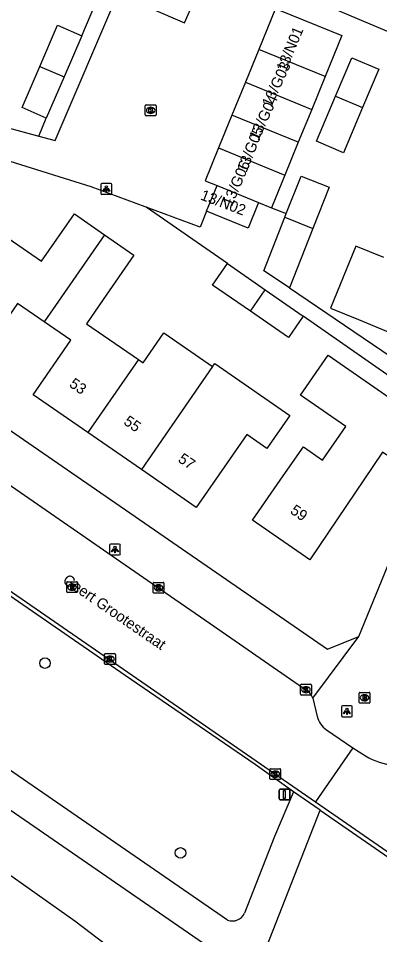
# Model space of a CAD drawing. Extents: x 162812 to 163818, y 381639 to 382470.
# Drawn here: x 163284.9 to 163318.4, y 381864.8 to 381949.7 of the extents above; entities that cross this region are included whole.
import ezdxf

# ---------------------------------------------------------------- set-up
doc = ezdxf.new("R2010")
doc.units = 0
for name, color, linetype in [('IMGEO_Boom', 7, 'Continuous'), ('IMGEO_Brandkraan', 7, 'Continuous'), ('IMGEO_Groenvoorziening', 7, 'Continuous'), ('IMGEO_Kolk', 7, 'Continuous'), ('IMGEO_Lichtpunt', 7, 'Continuous'), ('IMGEO_Openbare_ruimte_label', 7, 'Continuous'), ('IMGEO_Pand', 7, 'Continuous'), ('IMGEO_Pand_nummerreeks', 7, 'Continuous'), ('IMGEO_Rijbaan_lokaal_gesloten', 7, 'Continuous'), ('IMGEO_Rijbaan_lokaal_open', 7, 'Continuous'), ('IMGEO_Rioolput', 7, 'Continuous'), ('IMGEO_Verkeersbordpaal', 7, 'Continuous'), ('IMGEO_Voetpad_gesloten', 7, 'Continuous'), ('IMGEO_Voetpad_open', 7, 'Continuous')]:
    doc.layers.add(name, color=color, linetype=linetype)

msp = doc.modelspace()

# ---------------------------------------------------------------- linework, layer by layer
at = {"layer": 'IMGEO_Boom'}
for centre in [(163287.407, 381890.005), (163299.943, 381872.421)]:
    msp.add_circle(centre, 0.489, dxfattribs=at)
at = {"layer": 'IMGEO_Brandkraan'}
for p, q in [((163316.473, 381886.368), (163316.473, 381887.22)), ((163316.548, 381887.294), (163317.4, 381887.294)), ((163317.474, 381887.22), (163317.474, 381886.368)), ((163317.4, 381886.294), (163316.548, 381886.294)), ((163316.984, 381886.514), (163316.959, 381886.514)), ((163316.961, 381887.074), (163316.986, 381887.074))]:
    msp.add_line(p, q, dxfattribs=at)
for points in [[(163316.473, 381886.368), (163316.473, 381887.22)], [(163316.548, 381887.294), (163317.4, 381887.294)], [(163317.474, 381887.22), (163317.474, 381886.368)], [(163317.4, 381886.294), (163316.548, 381886.294)], [(163316.821, 381886.994), (163316.821, 381886.594), (163317.034, 381886.594)], [(163317.052, 381886.994), (163316.821, 381886.994)], [(163317, 381886.913), (163316.946, 381886.913), (163316.946, 381886.837)], [(163316.946, 381886.837), (163316.999, 381886.837)], [(163317.008, 381886.761), (163316.946, 381886.761), (163316.946, 381886.68)], [(163316.946, 381886.68), (163317.008, 381886.68)]]:
    msp.add_lwpolyline(points, dxfattribs=at)
for centre, radius, start, end in [((163316.55, 381887.218), 0.0765, 91.55205, 178.44795), ((163316.55, 381887.218), 0.0765, 91.55205, 178.44795), ((163317.398, 381887.218), 0.0765, 1.55205, 88.44795), ((163317.398, 381887.218), 0.0765, 1.55205, 88.44795), ((163316.55, 381886.37), 0.0765, 181.55205, 268.44795), ((163316.55, 381886.37), 0.0765, 181.55205, 268.44795), ((163317.001, 381886.875), 0.0379, 267.82845, 90.93552), ((163317.009, 381886.72), 0.0404, 269.87594, 90.50774), ((163317.04, 381886.845), 0.251, 268.66757, 293.53466), ((163317.056, 381886.849), 0.145, 59.4692, 91.53667), ((163317.081, 381886.896), 0.0922, 285.51372, 58.15012), ((163317.086, 381886.704), 0.105, 301.31148, 78.98903), ((163317.398, 381886.37), 0.0765, 271.55205, 358.44795), ((163317.398, 381886.37), 0.0765, 271.55205, 358.44795)]:
    msp.add_arc(centre, radius, start, end, dxfattribs=at)
for centre, major_axis, ratio, start_param, end_param in [((163316.96, 381886.794), (-0.387, 0.002), 0.722429, 4.712389, 7.853982), ((163316.985, 381886.794), (-0.39, 0.002), 0.717154, 1.570796, 4.712389)]:
    msp.add_ellipse(centre, major_axis=major_axis, ratio=ratio, start_param=start_param, end_param=end_param, dxfattribs=at)
at = {"layer": 'IMGEO_Groenvoorziening'}
msp.add_lwpolyline([(163279.685, 381873.538), (163290.178, 381866.115), (163314.756, 381847.403)], dxfattribs=at)
at = {"layer": 'IMGEO_Kolk'}
for p, q in [((163296.691, 381940.792), (163296.691, 381941.644)), ((163296.766, 381941.718), (163297.618, 381941.718)), ((163297.179, 381941.498), (163297.204, 381941.498)), ((163297.692, 381941.644), (163297.692, 381940.792)), ((163297.618, 381940.718), (163296.766, 381940.718)), ((163297.202, 381940.938), (163297.177, 381940.938)), ((163297.413, 381896.555), (163297.413, 381897.407)), ((163297.488, 381897.481), (163298.34, 381897.481)), ((163298.414, 381897.407), (163298.414, 381896.555)), ((163298.34, 381896.481), (163297.488, 381896.481)), ((163297.924, 381896.701), (163297.899, 381896.701)), ((163297.901, 381897.261), (163297.926, 381897.261)), ((163292.916, 381889.956), (163292.916, 381890.808)), ((163292.991, 381890.882), (163293.843, 381890.882)), ((163293.404, 381890.662), (163293.429, 381890.662)), ((163293.917, 381890.808), (163293.917, 381889.956)), ((163293.843, 381889.882), (163292.991, 381889.882)), ((163293.427, 381890.102), (163293.402, 381890.102)), ((163311.054, 381887.116), (163311.054, 381887.968)), ((163311.129, 381888.042), (163311.981, 381888.042)), ((163312.055, 381887.968), (163312.055, 381887.116)), ((163311.565, 381887.262), (163311.54, 381887.262)), ((163311.542, 381887.822), (163311.567, 381887.822)), ((163311.981, 381887.042), (163311.129, 381887.042)), ((163308.21, 381879.291), (163308.21, 381880.143)), ((163308.285, 381880.217), (163309.137, 381880.217)), ((163308.698, 381879.997), (163308.723, 381879.997)), ((163309.211, 381880.143), (163309.211, 381879.291)), ((163309.137, 381879.217), (163308.285, 381879.217)), ((163308.721, 381879.437), (163308.696, 381879.437))]:
    msp.add_line(p, q, dxfattribs=at)
for points in [[(163296.691, 381940.792), (163296.691, 381941.644)], [(163296.766, 381941.718), (163297.618, 381941.718)], [(163297.692, 381941.644), (163297.692, 381940.792)], [(163297.618, 381940.718), (163296.766, 381940.718)], [(163297.012, 381941.418), (163297.135, 381941.418), (163297.135, 381941.267), (163297.265, 381941.418), (163297.429, 381941.418), (163297.283, 381941.267), (163297.436, 381941.018), (163297.284, 381941.018), (163297.199, 381941.182), (163297.135, 381941.115), (163297.135, 381941.018), (163297.012, 381941.018), (163297.012, 381941.418)], [(163297.413, 381896.555), (163297.413, 381897.407)], [(163297.488, 381897.481), (163298.34, 381897.481)], [(163298.414, 381897.407), (163298.414, 381896.555)], [(163298.34, 381896.481), (163297.488, 381896.481)], [(163297.734, 381897.181), (163297.857, 381897.181), (163297.857, 381897.03), (163297.987, 381897.181), (163298.151, 381897.181), (163298.005, 381897.03), (163298.158, 381896.781), (163298.006, 381896.781), (163297.921, 381896.945), (163297.857, 381896.878), (163297.857, 381896.781), (163297.734, 381896.781), (163297.734, 381897.181)], [(163292.916, 381889.956), (163292.916, 381890.808)], [(163292.991, 381890.882), (163293.843, 381890.882)], [(163293.237, 381890.582), (163293.36, 381890.582), (163293.36, 381890.431), (163293.49, 381890.582), (163293.654, 381890.582), (163293.508, 381890.431), (163293.661, 381890.182), (163293.509, 381890.182), (163293.424, 381890.346), (163293.36, 381890.279), (163293.36, 381890.182), (163293.237, 381890.182), (163293.237, 381890.582)], [(163293.917, 381890.808), (163293.917, 381889.956)], [(163293.843, 381889.882), (163292.991, 381889.882)], [(163311.054, 381887.116), (163311.054, 381887.968)], [(163311.129, 381888.042), (163311.981, 381888.042)], [(163312.055, 381887.968), (163312.055, 381887.116)], [(163311.375, 381887.742), (163311.498, 381887.742), (163311.498, 381887.591), (163311.628, 381887.742), (163311.792, 381887.742), (163311.646, 381887.591), (163311.799, 381887.342), (163311.647, 381887.342), (163311.562, 381887.506), (163311.498, 381887.439), (163311.498, 381887.342), (163311.375, 381887.342), (163311.375, 381887.742)], [(163311.981, 381887.042), (163311.129, 381887.042)], [(163308.21, 381879.291), (163308.21, 381880.143)], [(163308.285, 381880.217), (163309.137, 381880.217)], [(163308.531, 381879.917), (163308.654, 381879.917), (163308.654, 381879.766), (163308.784, 381879.917), (163308.948, 381879.917), (163308.802, 381879.766), (163308.955, 381879.517), (163308.803, 381879.517), (163308.718, 381879.681), (163308.654, 381879.614), (163308.654, 381879.517), (163308.531, 381879.517), (163308.531, 381879.917)], [(163309.211, 381880.143), (163309.211, 381879.291)], [(163309.137, 381879.217), (163308.285, 381879.217)]]:
    msp.add_lwpolyline(points, dxfattribs=at)
for centre, start, end in [((163296.768, 381941.642), 91.55205, 178.44795), ((163296.768, 381941.642), 91.55205, 178.44795), ((163297.616, 381941.642), 1.55205, 88.44795), ((163297.616, 381941.642), 1.55205, 88.44795), ((163296.768, 381940.794), 181.55205, 268.44795), ((163296.768, 381940.794), 181.55205, 268.44795), ((163297.616, 381940.794), 271.55205, 358.44795), ((163297.616, 381940.794), 271.55205, 358.44795), ((163297.49, 381897.405), 91.55205, 178.44795), ((163297.49, 381897.405), 91.55205, 178.44795), ((163298.338, 381897.405), 1.55205, 88.44795), ((163298.338, 381897.405), 1.55205, 88.44795), ((163297.49, 381896.557), 181.55205, 268.44795), ((163297.49, 381896.557), 181.55205, 268.44795), ((163298.338, 381896.557), 271.55205, 358.44795), ((163298.338, 381896.557), 271.55205, 358.44795), ((163292.993, 381890.806), 91.55205, 178.44795), ((163292.993, 381890.806), 91.55205, 178.44795), ((163293.841, 381890.806), 1.55205, 88.44795), ((163293.841, 381890.806), 1.55205, 88.44795), ((163292.993, 381889.958), 181.55205, 268.44795), ((163292.993, 381889.958), 181.55205, 268.44795), ((163293.841, 381889.958), 271.55205, 358.44795), ((163293.841, 381889.958), 271.55205, 358.44795), ((163311.131, 381887.966), 91.55205, 178.44795), ((163311.131, 381887.966), 91.55205, 178.44795), ((163311.979, 381887.966), 1.55205, 88.44795), ((163311.979, 381887.966), 1.55205, 88.44795), ((163311.131, 381887.118), 181.55205, 268.44795), ((163311.131, 381887.118), 181.55205, 268.44795), ((163311.979, 381887.118), 271.55205, 358.44795), ((163311.979, 381887.118), 271.55205, 358.44795), ((163308.287, 381880.141), 91.55205, 178.44795), ((163308.287, 381880.141), 91.55205, 178.44795), ((163309.135, 381880.141), 1.55205, 88.44795), ((163309.135, 381880.141), 1.55205, 88.44795), ((163308.287, 381879.293), 181.55205, 268.44795), ((163308.287, 381879.293), 181.55205, 268.44795), ((163309.135, 381879.293), 271.55205, 358.44795), ((163309.135, 381879.293), 271.55205, 358.44795)]:
    msp.add_arc(centre, 0.0765, start, end, dxfattribs=at)
for centre, major_axis, ratio, start_param, end_param in [((163297.178, 381941.218), (-0.387, 0.002), 0.722429, 4.712389, 7.853982), ((163297.203, 381941.218), (-0.39, 0.002), 0.717154, 1.570796, 4.712389), ((163297.9, 381896.981), (-0.387, 0.002), 0.722429, 4.712389, 7.853982), ((163297.925, 381896.981), (-0.39, 0.002), 0.717154, 1.570796, 4.712389), ((163293.403, 381890.382), (-0.387, 0.002), 0.722429, 4.712389, 7.853982), ((163293.428, 381890.382), (-0.39, 0.002), 0.717154, 1.570796, 4.712389), ((163311.541, 381887.542), (-0.387, 0.002), 0.722429, 4.712389, 7.853982), ((163311.566, 381887.542), (-0.39, 0.002), 0.717154, 1.570796, 4.712389), ((163308.697, 381879.717), (-0.387, 0.002), 0.722429, 4.712389, 7.853982), ((163308.722, 381879.717), (-0.39, 0.002), 0.717154, 1.570796, 4.712389)]:
    msp.add_ellipse(centre, major_axis=major_axis, ratio=ratio, start_param=start_param, end_param=end_param, dxfattribs=at)
at = {"layer": 'IMGEO_Lichtpunt'}
for p, q in [((163292.585, 381934.337), (163292.585, 381933.53)), ((163292.585, 381934.337), (163292.585, 381933.53)), ((163293.487, 381934.432), (163292.679, 381934.432)), ((163293.487, 381934.432), (163292.679, 381934.432)), ((163293.581, 381933.53), (163293.581, 381934.337)), ((163293.581, 381933.53), (163293.581, 381934.337)), ((163292.679, 381933.436), (163293.487, 381933.436)), ((163292.679, 381933.436), (163293.487, 381933.436)), ((163293.383, 381900.937), (163293.383, 381900.13)), ((163293.383, 381900.937), (163293.383, 381900.13)), ((163294.285, 381901.032), (163293.477, 381901.032)), ((163294.285, 381901.032), (163293.477, 381901.032)), ((163294.379, 381900.13), (163294.379, 381900.937)), ((163294.379, 381900.13), (163294.379, 381900.937)), ((163293.477, 381900.036), (163294.285, 381900.036)), ((163293.477, 381900.036), (163294.285, 381900.036)), ((163314.846, 381885.943), (163314.846, 381885.136)), ((163314.846, 381885.943), (163314.846, 381885.136)), ((163315.748, 381886.038), (163314.94, 381886.038)), ((163315.748, 381886.038), (163314.94, 381886.038)), ((163315.842, 381885.136), (163315.842, 381885.943)), ((163315.842, 381885.136), (163315.842, 381885.943)), ((163314.94, 381885.042), (163315.748, 381885.042)), ((163314.94, 381885.042), (163315.748, 381885.042))]:
    msp.add_line(p, q, dxfattribs=at)
for points in [[(163292.959, 381934.001), (163292.998, 381933.973), (163292.81, 381933.711), (163292.772, 381933.738), (163292.959, 381934.001)], [(163293.061, 381933.953), (163293.108, 381933.953), (163293.108, 381933.631), (163293.061, 381933.631), (163293.061, 381933.953)], [(163293.171, 381933.973), (163293.209, 381934), (163293.396, 381933.738), (163293.357, 381933.71), (163293.171, 381933.973)], [(163293.757, 381900.601), (163293.796, 381900.573), (163293.608, 381900.311), (163293.57, 381900.338), (163293.757, 381900.601)], [(163293.859, 381900.553), (163293.906, 381900.553), (163293.906, 381900.231), (163293.859, 381900.231), (163293.859, 381900.553)], [(163293.969, 381900.573), (163294.007, 381900.6), (163294.194, 381900.338), (163294.155, 381900.31), (163293.969, 381900.573)], [(163315.22, 381885.607), (163315.259, 381885.579), (163315.071, 381885.317), (163315.033, 381885.344), (163315.22, 381885.607)], [(163315.322, 381885.559), (163315.369, 381885.559), (163315.369, 381885.237), (163315.322, 381885.237), (163315.322, 381885.559)], [(163315.432, 381885.579), (163315.47, 381885.606), (163315.657, 381885.344), (163315.618, 381885.316), (163315.432, 381885.579)]]:
    msp.add_lwpolyline(points, dxfattribs=at)
for centre in [(163293.084, 381934.135), (163293.882, 381900.735), (163315.345, 381885.741)]:
    msp.add_circle(centre, 0.0994, dxfattribs=at)
for centre, start, end in [((163292.679, 381934.337), 90, 180), ((163292.679, 381934.337), 90, 180), ((163293.487, 381934.337), 0, 90), ((163293.487, 381934.337), 0, 90), ((163292.679, 381933.53), 180, 270), ((163292.679, 381933.53), 180, 270), ((163293.487, 381933.53), 270, 0), ((163293.487, 381933.53), 270, 360), ((163293.477, 381900.937), 90, 180), ((163293.477, 381900.937), 90, 180), ((163294.285, 381900.937), 0, 90), ((163294.285, 381900.937), 0, 90), ((163293.477, 381900.13), 180, 270), ((163293.477, 381900.13), 180, 270), ((163294.285, 381900.13), 270, 0), ((163294.285, 381900.13), 270, 360), ((163314.94, 381885.943), 90, 180), ((163314.94, 381885.943), 90, 180), ((163315.748, 381885.943), 0, 90), ((163315.748, 381885.943), 0, 90), ((163314.94, 381885.136), 180, 270), ((163314.94, 381885.136), 180, 270), ((163315.748, 381885.136), 270, 0), ((163315.748, 381885.136), 270, 360)]:
    msp.add_arc(centre, 0.0946, start, end, dxfattribs=at)
at = {"layer": 'IMGEO_Pand'}
for points in [[(163297.235, 381950.668), (163300.324, 381949.325), (163302.999, 381955.478)], [(163309.024, 381950.542), (163308.747, 381950.655), (163307.195, 381946.864)], [(163309.024, 381950.542), (163314.886, 381948.141), (163313.334, 381944.351)], [(163286.924, 381945.283), (163288.56, 381949.095), (163290.804, 381948.132)], [(163290.804, 381948.132), (163289.168, 381944.321)], [(163307.195, 381946.864), (163305.95, 381943.822)], [(163313.334, 381944.351), (163307.195, 381946.864)], [(163314.288, 381942.519), (163315.806, 381946.095), (163318.302, 381945.036), (163316.799, 381941.491)], [(163287.531, 381940.508), (163285.288, 381941.471), (163286.924, 381945.283)], [(163286.924, 381945.283), (163289.168, 381944.321)], [(163289.168, 381944.321), (163287.531, 381940.508)], [(163313.334, 381944.351), (163312.088, 381941.309)], [(163305.95, 381943.822), (163304.704, 381940.78)], [(163305.95, 381943.822), (163312.088, 381941.309)], [(163316.799, 381941.491), (163315.018, 381937.295), (163312.521, 381938.354), (163314.288, 381942.519)], [(163314.288, 381942.519), (163316.799, 381941.491)], [(163304.704, 381940.78), (163303.458, 381937.739)], [(163310.843, 381938.267), (163304.704, 381940.78)], [(163312.088, 381941.309), (163310.843, 381938.267)], [(163310.843, 381938.267), (163309.598, 381935.225)], [(163303.458, 381937.739), (163302.213, 381934.697), (163303.327, 381934.241)], [(163303.458, 381937.739), (163309.598, 381935.225)], [(163309.598, 381935.225), (163308.358, 381932.197)], [(163309.738, 381931.65), (163311.106, 381935.117), (163313.706, 381934.091), (163312.199, 381930.271)], [(163302.355, 381931.866), (163303.327, 381934.241)], [(163303.327, 381934.241), (163307.172, 381932.682)], [(163307.172, 381932.682), (163306.194, 381930.294), (163302.355, 381931.866)], [(163307.172, 381932.682), (163308.358, 381932.197)], [(163280.947, 381928.569), (163282.283, 381930.555), (163287.091, 381927.23), (163290.128, 381931.623), (163292.911, 381929.699)], [(163310.033, 381924.777), (163307.643, 381926.338), (163309.612, 381931.33)], [(163309.612, 381931.33), (163309.738, 381931.65)], [(163309.612, 381931.33), (163312.199, 381930.271)], [(163292.911, 381929.699), (163287.322, 381921.628)], [(163292.911, 381929.699), (163295.64, 381927.812), (163292.797, 381923.7), (163291.24, 381921.447), (163296.05, 381918.122)], [(163312.199, 381930.271), (163310.033, 381924.777)], [(163318.773, 381927.579), (163316.169, 381928.645), (163313.815, 381922.896), (163316.419, 381921.83), (163319.38, 381920.618), (163324.007, 381918.723), (163326.361, 381924.472)], [(163306.42, 381922.605), (163302.91, 381925.033), (163304.283, 381927.018)], [(163304.283, 381927.018), (163307.793, 381924.59)], [(163306.42, 381922.605), (163307.793, 381924.59)], [(163307.793, 381924.59), (163311.302, 381922.163)], [(163287.322, 381921.628), (163284.851, 381923.335), (163281.365, 381918.292), (163276.283, 381921.805)], [(163311.302, 381922.163), (163309.929, 381920.178), (163306.42, 381922.605)], [(163291.38, 381911.364), (163286.305, 381914.872), (163289.794, 381919.919), (163287.322, 381921.628)], [(163296.05, 381918.122), (163296.477, 381917.827), (163298.397, 381920.603), (163302.92, 381917.476)], [(163311.057, 381914.819), (163313.615, 381918.52), (163318.955, 381914.83), (163321.613, 381912.993), (163319.046, 381909.279), (163318.645, 381909.556), (163311.926, 381899.566), (163306.613, 381903.239), (163309.457, 381907.353), (163311.314, 381910.04), (163313.092, 381908.811), (163315.245, 381911.924), (163311.057, 381914.819)], [(163296.05, 381918.122), (163291.38, 381911.364)], [(163302.92, 381917.476), (163303.116, 381917.759), (163310.061, 381912.957), (163307.945, 381909.897), (163306.077, 381911.189), (163304.25, 381908.546), (163301.406, 381904.433), (163296.331, 381907.941)], [(163302.92, 381917.476), (163296.331, 381907.941)], [(163296.331, 381907.941), (163291.38, 381911.364)]]:
    msp.add_lwpolyline(points, dxfattribs=at)
at = {"layer": 'IMGEO_Rijbaan_lokaal_gesloten'}
for points in [[(163266.914, 381908.622), (163295.088, 381889.16)], [(163280.586, 381908.97), (163298.526, 381896.557), (163301.786, 381894.301), (163311.737, 381887.416)], [(163295.088, 381889.16), (163312.423, 381877.143)], [(163312.179, 381886.77), (163312.585, 381885.073)], [(163313.455, 381883.83), (163315.902, 381882.141)]]:
    msp.add_lwpolyline(points, dxfattribs=at)
for centre, radius, start, end in [((163310.87, 381886.348), 1.375, 17.84781, 50.91288), ((163314.615, 381885.568), 2.089, 193.69881, 236.27905)]:
    msp.add_arc(centre, radius, start, end, dxfattribs=at)
at = {"layer": 'IMGEO_Rijbaan_lokaal_open'}
for points in [[(163286.824, 381938.835), (163288.359, 381938.418), (163294.145, 381952.011)], [(163277.734, 381941.306), (163286.824, 381938.835)], [(163296.762, 381932.249), (163296.673, 381932.282), (163291.676, 381934.146), (163284.175, 381936.467)], [(163302.355, 381931.866), (163301.752, 381930.388), (163296.762, 381932.249)], [(163310.399, 381878.067), (163306.85, 381880.597), (163294.84, 381888.868), (163276.348, 381901.602)], [(163315.902, 381882.141), (163312.423, 381877.143)], [(163315.902, 381882.141), (163317.069, 381881.407)], [(163312.858, 381876.368), (163310.399, 381878.067)], [(163312.423, 381877.143), (163328.942, 381865.735)], [(163312.858, 381876.368), (163356.676, 381846.092)]]:
    msp.add_lwpolyline(points, dxfattribs=at)
msp.add_arc((163320.212, 381886.552), 6.029, 238.57959, 344.14571, dxfattribs=at)
at = {"layer": 'IMGEO_Rioolput'}
for p, q in [((163289.416, 381896.619), (163289.416, 381897.471)), ((163289.491, 381897.545), (163290.343, 381897.545)), ((163289.904, 381897.325), (163289.929, 381897.325)), ((163290.417, 381897.471), (163290.417, 381896.619)), ((163290.343, 381896.545), (163289.491, 381896.545)), ((163289.927, 381896.765), (163289.902, 381896.765))]:
    msp.add_line(p, q, dxfattribs=at)
for points in [[(163289.416, 381896.619), (163289.416, 381897.471)], [(163289.491, 381897.545), (163290.343, 381897.545)], [(163290.417, 381897.471), (163290.417, 381896.619)], [(163290.343, 381896.545), (163289.491, 381896.545)], [(163290.005, 381897.243), (163289.753, 381897.245), (163289.753, 381896.845)], [(163289.753, 381896.845), (163289.877, 381896.845), (163289.877, 381897.007), (163289.888, 381897.007)], [(163289.931, 381897.164), (163289.877, 381897.164), (163289.877, 381897.083)], [(163289.877, 381897.083), (163289.929, 381897.083)], [(163289.935, 381896.978), (163290.006, 381896.845), (163290.146, 381896.845), (163290.081, 381896.971)]]:
    msp.add_lwpolyline(points, dxfattribs=at)
for centre, radius, start, end in [((163289.493, 381897.469), 0.0765, 91.55205, 178.44795), ((163289.493, 381897.469), 0.0765, 91.55205, 178.44795), ((163290.341, 381897.469), 0.0765, 1.55205, 88.44795), ((163290.341, 381897.469), 0.0765, 1.55205, 88.44795), ((163289.493, 381896.621), 0.0765, 181.55205, 268.44795), ((163289.493, 381896.621), 0.0765, 181.55205, 268.44795), ((163289.887, 381896.954), 0.0533, 26.02933, 88.69889), ((163289.913, 381897.272), 0.19, 274.7715, 282.96867), ((163289.937, 381897.068), 0.0964, 77.00612, 93.18647), ((163289.951, 381897.125), 0.0378, 276.66336, 79.67722), ((163290.004, 381897.133), 0.109, 350.36119, 89.41601), ((163290.002, 381897.133), 0.112, 277.58423, 350.98172), ((163289.986, 381896.918), 0.108, 29.51342, 73.79051), ((163290.341, 381896.621), 0.0765, 271.55205, 358.44795), ((163290.341, 381896.621), 0.0765, 271.55205, 358.44795)]:
    msp.add_arc(centre, radius, start, end, dxfattribs=at)
for centre, major_axis, ratio, start_param, end_param in [((163289.903, 381897.045), (-0.387, 0.002), 0.722429, 4.712389, 7.853982), ((163289.928, 381897.045), (-0.39, 0.002), 0.717154, 1.570796, 4.712389)]:
    msp.add_ellipse(centre, major_axis=major_axis, ratio=ratio, start_param=start_param, end_param=end_param, dxfattribs=at)
at = {"layer": 'IMGEO_Verkeersbordpaal'}
for p, q in [((163309.066, 381877.428), (163309.066, 381878.228)), ((163309.066, 381878.228), (163309.066, 381877.428)), ((163309.166, 381878.328), (163309.956, 381878.328)), ((163309.956, 381878.328), (163309.166, 381878.328)), ((163310.056, 381878.228), (163310.056, 381877.428)), ((163310.056, 381877.428), (163310.056, 381878.228)), ((163309.956, 381877.328), (163309.166, 381877.328)), ((163309.166, 381877.328), (163309.956, 381877.328))]:
    msp.add_line(p, q, dxfattribs=at)
msp.add_lwpolyline([(163309.486, 381878.203), (163309.636, 381878.203), (163309.636, 381877.453), (163309.486, 381877.453), (163309.486, 381878.203)], dxfattribs=at)
for centre, start, end in [((163309.166, 381878.228), 90, 180), ((163309.166, 381878.228), 90, 180), ((163309.956, 381878.228), 0, 90), ((163309.956, 381878.228), 360, 90), ((163309.166, 381877.428), 180, 270), ((163309.166, 381877.428), 180, 270), ((163309.956, 381877.428), 270, 0), ((163309.956, 381877.428), 270, 0)]:
    msp.add_arc(centre, 0.1, start, end, dxfattribs=at)
at = {"layer": 'IMGEO_Voetpad_gesloten'}
for points in [[(163304.295, 381866.201), (163269.21, 381890.392)], [(163281.469, 381878.258), (163340.759, 381837.344)], [(163310.399, 381878.067), (163308.631, 381873.943), (163305.876, 381866.829)], [(163342.853, 381839.72), (163307.889, 381863.692), (163312.858, 381876.368)]]:
    msp.add_lwpolyline(points, dxfattribs=at)
msp.add_arc((163304.748, 381867.364), 1.248, 248.71378, 334.61385, dxfattribs=at)
at = {"layer": 'IMGEO_Voetpad_open'}
for points in [[(163337.762, 381940.645), (163309.811, 381952.487)], [(163290.804, 381948.132), (163292.111, 381951.177)], [(163286.824, 381938.835), (163287.531, 381940.508)], [(163304.283, 381927.018), (163296.762, 381932.249)], [(163308.358, 381932.197), (163309.738, 381931.65)], [(163310.033, 381924.777), (163325.4, 381914.344)], [(163324.747, 381912.749), (163311.302, 381922.163)], [(163316.437, 381892.468), (163324.747, 381912.749)], [(163284.116, 381911.615), (163313.54, 381891.287), (163316.437, 381892.468)], [(163312.179, 381886.77), (163316.437, 381892.468)]]:
    msp.add_lwpolyline(points, dxfattribs=at)

# ---------------------------------------------------------------- texts
at = {"layer": 'IMGEO_Openbare_ruimte_label'}
msp.add_text('Geert Grootestraat', height=1, rotation=325.46788, dxfattribs=at).set_placement((163288.962, 381897.495))
at = {"layer": 'IMGEO_Pand_nummerreeks'}
for s, rotation, p in [('13/N01', 67.38014, (163309.686, 381944.721)), ('13/G03', 65.15761, (163308.333, 381941.449)), ('13/G04', 65.09523, (163307.145, 381938.372)), ('13/G05', 68.19859, (163306.047, 381935.399)), ('13/G06', 66.91487, (163304.699, 381932.256)), ('13/N02', 339.31592, (163301.718, 381932.974)), ('53', 325.34472, (163289.576, 381915.676)), ('55', 325.34751, (163294.609, 381912.196)), ('57', 325.34751, (163299.642, 381908.716)), ('59', 325.34178, (163310.023, 381903.946))]:
    msp.add_text(s, height=1, rotation=rotation, dxfattribs=at).set_placement(p)

doc.saveas('drawing.dxf')
